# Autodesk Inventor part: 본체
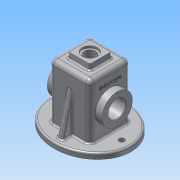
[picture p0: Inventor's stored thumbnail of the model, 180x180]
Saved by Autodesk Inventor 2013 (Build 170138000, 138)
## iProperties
Created: 2017-07
Part Number: 본체
Material: 알루미늄 6061
Document SubType Name: Modeling
Designer: Administrator
Density: 2.71 g/cm^3
Mass: 892.77 g
Surface Area: 987.448 cm^2
Volume: 329.435 cm^3
Author: Administrator
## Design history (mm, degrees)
sketch "스케치2"
  geometry: L1 (37, -37)-(-37, -37); L2 (-37, -37)-(-37, 37); L3 (-37, 37)-(37, 37); L4 (37, 37)-(37, -37); L5 (37, -37)-(-37, 37); L6 (-37, -37)-(37, 37); 1 further point
  constraints: 12 end point, 2 midpoint, 2 parallel, 1 horizontal, 1 perpendicular
  dimensions: "d0" = 74 distance of L2.end L3.end; "d2" = 74 distance of L1.end L2.end
extrude "돌출1" new body sketch "스케치2" distance "d3" = 100; taper "d4" = 0 deg
feature "쉘1" dims "d5" = 5
fillet "모깎기1" dims "d6" = 3
fillet "모깎기2" dims "d7" = 8
sketch "스케치4" dims "d8" = 65, "d10" = 75
  geometry: L1 (29, 29)-(29, -29) reference; L2 (-29, 29)-(29, 29) reference; L3 (-29, -29)-(-29, 29) reference; L4 (29, -29)-(-29, -29) reference; L5 (0, 0)-(-58, 0); L6 (0, 0)-(58, 0); L7 (-29, -32)-(29, -32) reference; L8 (32, -29)-(32, 29) reference; L9 (29, 32)-(-29, 32) reference; L10 (-32, 29)-(-32, -29) reference; L11 (37, 29)-(37, -29) reference; L12 (29, -37)-(-29, -37) reference; L13 (-37, -29)-(-37, 29) reference; L14 (-29, 37)-(29, 37) reference; C1 r 5 at (-58, 0); C2 r 5 at (58, 0); A1 r 3 centre (29, -29) between (29, -32) and (32, -29) reference; A2 r 3 centre (29, 29) between (32, 29) and (29, 32) reference; A3 r 3 centre (-29, 29) between (-29, 32) and (-32, 29) reference; A4 r 3 centre (-29, -29) between (-32, -29) and (-29, -32) reference; A5 r 8 centre (29, 29) between (37, 29) and (29, 37) reference; A6 r 8 centre (29, -29) between (29, -37) and (37, -29) reference; A7 r 8 centre (-29, -29) between (-37, -29) and (-29, -37) reference; A8 r 8 centre (-29, 29) between (-29, 37) and (-37, 29) reference; 2 further points; 1 other entity
  constraints: 4 coincident, 4 end point, 2 centre point, 2 horizontal, 1 collinear, 2 other
  dimensions: "d11" = 58 distance of L5.start L5.end; "d12" = 10 diameter of C1; "d13" = 58 distance of L5.start L6.end; "d14" = 10 diameter of C2
  node "투영된 루프1"
  node "투영된 루프3"
sketch "스케치5"
  geometry: L1 (92, -36)-(92, 94) reference; L2 (92, 29)-(47, 29); C1 r 27.5 at (47, 29); 1 further point
  constraints: 2 end point, 1 centre point, 1 coincident, 1 midpoint, 1 perpendicular
  dimensions: "d18" = 45 distance of L2.start L2.end; "d20" = 55 diameter of C1
extrude "돌출3" join sketch "스케치5" distance "d21" = 13; taper "d22" = 0 deg
fillet "모깎기4" dims "d23" = 0.5
sketch "스케치6"
  geometry: L1 (-92, 94)-(-92, -36) reference; L2 (-92, 29)-(-47, 29); C1 r 27.5 at (-47, 29); 1 further point
  constraints: 2 end point, 1 centre point, 1 coincident, 1 midpoint, 1 perpendicular
  dimensions: "d24" = 45 distance of L2.start L2.end; "d26" = 55 diameter of C1
extrude "돌출4" join sketch "스케치6" distance "d27" = 13; taper "d28" = 0 deg
fillet "모깎기5" dims "d29" = 0.5
sketch "스케치7"
  geometry: C1 r 27.5 at (0, 0) reference; C2 r 16 at (0, 0); 1 further point
  constraints: 1 centre point, 1 coincident
  dimensions: "d30" = 32 diameter of C2
extrude "돌출5" cut sketch "스케치7" stored distance "d32" = 13; taper "d33" = 0 deg
chamfer "모따기1" distance "d34" = 1; stored, may be unused: second distance "d35" = 2, angle "d36" = 45 deg
sketch "스케치8"
  geometry: L1 (29, -10)-(-29, -10) reference; L2 (-50, 62)-(-50, 28) reference; L3 (50, 28)-(50, 62) reference; L4 (-50, 45)-(50, 45); L5 (-49, 61)-(-32, 61) reference; L6 (50, 17.5)-(50, 72.5) reference; L7 (37.5, 72.5)-(37.5, 17.5) reference; L8 (32, 61)-(49, 61) reference; L9 (-32, 92)-(-32, 0) reference; L10 (32, 0)-(32, 92) reference; L11 (-32, 45)-(-32, 61); L12 (-32, 61)-(-25, 61); L13 (-32, 72.5)-(-25, 65.5); L14 (-25, 61)-(-25, 65.5); L15 (32, 45)-(32, 61); L16 (32, 61)-(25, 61); L17 (25, 61)-(25, 65.5); L18 (25, 65.5)-(32, 72.5); L19 (-32, 61)-(-32, 72.5); L20 (32, 61)-(32, 72.5); 1 further point
  constraints: 22 end point, 6 point on line, 5 perpendicular, 4 collinear, 2 midpoint
  dimensions: "d37" = 7 distance of L5.end L12.end; "d39" = 55 diameter of L13.start L4; "d40" = 135 deg angle of L9 L13; "d41" = 7 distance of L8.start L16.end; "d42" = 4.5 distance of L16.end L17.end
  node "투영된 루프2"
revolve "회전1" stored, may be unused: angle "d43" = 90 deg
extrude "돌출6" join sketch "스케치4" distance "d44" = 10; taper "d45" = 0 deg
fillet "모깎기6" dims "d46" = 3
fillet "모깎기7" dims "d47" = 0.5
revolve "회전2" stored, may be unused: angle "d48" = 90 deg
fillet "모깎기8" dims "d49" = 0.5
sketch "스케치9"
  geometry: L1 (-17, -20)-(17, -20); L2 (20, -17)-(20, 17); L3 (17, 20)-(-17, 20); L4 (-20, 17)-(-20, -17); L5 (-20, -20)-(20, 20); L6 (20, -20)-(-20, 20); A1 r 3 centre (-17, 17) between (-17, 20) and (-20, 17); A2 r 3 centre (-17, -17) between (-20, -17) and (-17, -20); A3 r 3 centre (17, -17) between (17, -20) and (20, -17); A4 r 3 centre (17, 17) between (20, 17) and (17, 20); 1 further point
  constraints: 12 end point, 8 point on circle, 8 point on line, 8 tangent, 4 centre point, 3 equal radius, 2 midpoint, 2 parallel, 1 horizontal, 1 perpendicular
  dimensions: "d52" = 40 distance of L5.end L6.end; "d54" = 40 distance of L6.end L5.start; "d55" = 3 radius of A1
extrude "돌출7" join sketch "스케치9" distance "d56" = 10; taper "d57" = -5 deg
fillet "모깎기9" dims "d58" = 3
sketch "스케치10"
  geometry: C1 r 14 at (0, 0); 1 further point
  constraints: 1 centre point, 1 coincident
  dimensions: "d59" = 28 diameter of C1
extrude "돌출8" cut sketch "스케치10" distance "d61" = 4; taper "d62" = 0 deg
sketch "스케치11"
  geometry: C1 r 14 at (0, 0) reference; C2 r 10.5 at (0, 0)
  constraints: 1 centre point, 1 coincident
  dimensions: "d63" = 21 diameter of C2
extrude "돌출9" cut sketch "스케치11" stored distance "d65" = 4; taper "d66" = 0 deg
sketch "스케치12" dims "d67" = 45
  geometry: L1 (0, 0)-(0, 22.5); C1 r 17 at (0, 0) reference; C2 r 2 at (0, 22.5); 1 further point
  constraints: 2 coincident, 2 end point, 1 centre point, 1 vertical, 1 vertical alignment, 2 other
  dimensions: "d69" = 4 diameter of C2
hole "구멍1" sketch "스케치12" at (0, 22.5) diameter "d70" = 3.242; stored, may be unused: countersink angle "d74" = 90 deg, drill point angle "d76" = 118 deg; dims "d71" = 8, "d72" = 4, "d73" = 2, "d75" = 10
sketch "스케치13" dims "d80" = 45
  geometry: L1 (0, 0)-(0, 22.5); C1 r 17 at (0, 0) reference; C2 r 2 at (0, 22.5); 1 further point
  constraints: 2 coincident, 2 end point, 1 centre point, 1 vertical, 1 vertical alignment, 2 other
  dimensions: "d82" = 4 diameter of C2
hole "구멍2" sketch "스케치13" at (0, 22.5) diameter "d83" = 3.242; stored, may be unused: countersink angle "d87" = 90 deg, drill point angle "d89" = 118 deg; dims "d84" = 8, "d85" = 4, "d86" = 2, "d88" = 10
sketch "스케치14"
  geometry: L1 (-37, 0)-(-37, 92) reference; L2 (37, 92)-(37, 0) reference; L3 (29, -10)-(-29, -10) reference; L4 (-65, -10)-(65, -10) reference; L5 (-65, -10)-(-65, 0); L6 (-55, 0)-(-55, -10); L7 (-65, 0)-(-55, 0); L8 (-55, 0)-(-37, 72.194); L9 (65, -10)-(65, 0); L10 (55, -10)-(55, 0); L11 (65, 0)-(55, 0); L12 (55, 0)-(37, 72.194); L13 (-37, 72.194)-(-37, 0); L14 (37, 72.194)-(37, 0); L15 (55, 0)-(37, 0); L16 (-37, 0)-(-55, 0); 1 further point
  constraints: 24 end point, 5 point on line, 4 perpendicular, 2 collinear, 1 vertical
  dimensions: "d95" = 10 distance of L4.start L5.end; "d96" = 10 distance between parallel lines of L5 L6; "d98" = 10 distance of L6.start L6.end; "d99" = 14 deg angle of L5 L8; "d100" = 10 distance of L4.end L9.end; "d102" = 10 distance of L10.start L10.end; "d103" = 10 distance between parallel lines of L9 L10; "d104" = 14 deg angle of L9 L12
extrude "돌출10" join sketch "스케치14" stored distance "d105" = 10; taper "d106" = 0 deg
fillet "모깎기10" dims "d107" = 3
fillet "모깎기11" dims "d108" = 3
sketch "스케치15"
  geometry: L1 (7.189, 8.261)-(7.189, 49.739); L2 (7.189, 49.739)-(16.811, 49.739); L3 (16.811, 49.739)-(16.811, 8.261); L4 (16.811, 8.261)-(7.189, 8.261); L5 (12, 8.261)-(12, 49.739); L6 (7.189, 29)-(16.811, 29); L7 (89, 66)-(0, 66) reference; L8 (-8, 58)-(-8, 0) reference; L9 (-18, 46)-(-18, 12) reference; 1 further point
  constraints: 4 end point, 4 midpoint, 2 other
  dimensions: "d109" = 37 distance between parallel lines of L7 L6; "d111" = 30 distance between parallel lines of L9 L5
extrude "돌출11" join sketch "스케치15" distance "d112" = 0.5; taper "d113" = 0 deg
node "솔리드1"
pattern_circular "원형 패턴1" dims angle "d78" = 360 deg
pattern_circular "원형 패턴2" dims "d91" = 360 deg
